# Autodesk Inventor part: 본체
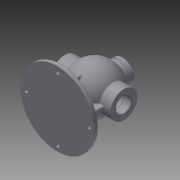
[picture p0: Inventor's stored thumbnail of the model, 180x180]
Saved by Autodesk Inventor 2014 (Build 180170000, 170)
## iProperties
Created: 2020-08
Part Number: 본체
Material: Generic
Document SubType Name: Modeling
Designer: kh
Density: 1 g/cm^3
Appearance: Default
Author: kh
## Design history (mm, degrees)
sketch "Sketch1"
  geometry: L1 (-53, 85)-(53, 85); A1 r 53 centre (0, 85) between (53, 85) and (-53, 85); 2 further points
  constraints: 2 end point, 2 horizontal alignment, 2 point on circle, 1 centre point, 1 midpoint, 1 vertical alignment
  dimensions: "d0" = 106 diameter of A1; "d1" = 85 distance of point (0, 0) A1.centre
revolve "Revolution1" sketch "Sketch1" stored, may be unused: angle "d2" = 90 deg
shell "Shell1" dims "d3" = 10
sketch "Sketch2"
  geometry: C1 r 85 at (0, 0); 1 further point
  constraints: 1 centre point, 1 coincident
  dimensions: "d4" = 170 diameter of C1
extrude "Extrusion1" join sketch "Sketch2" distance "d5" = 10; taper "d6" = 0 deg
workplane "Work Plane1"
sketch "Sketch3"
  geometry: C1 r 31 at (85, 0); 1 further point
  constraints: 1 centre point, 1 horizontal alignment
  dimensions: "d8" = 62 diameter of C1; "d9" = 85 distance of C1.centre point (0, 0)
extrude "Extrusion2" join sketch "Sketch3" stored distance "d10" = 10; taper "d11" = 0 deg
sketch "Sketch4"
  geometry: C1 r 31 at (0, 0) reference; C2 r 17.5 at (0, 0); 1 further point
  constraints: 1 centre point, 1 coincident
  dimensions: "d12" = 35 diameter of C2
extrude "Extrusion3" cut sketch "Sketch4" stored distance "d13" = 10; taper "d14" = 0 deg
sketch "Sketch5" dims "d15" = 48
  geometry: L1 (0, 0)-(0, 24); C1 r 31 at (0, 0) reference; 2 further points
  constraints: 2 coincident, 2 end point, 1 vertical, 1 vertical alignment, 2 other
hole "Hole1" sketch "Sketch5" at (0, 24) diameter "d16" = 3.242; stored, may be unused: countersink angle "d20" = 90 deg, drill point angle "d22" = 118 deg; dims "d17" = 12, "d18" = 4, "d19" = 2, "d21" = 15
pattern_circular "Circular Pattern1" dims angle "d24" = 360 deg
mirror "Mirror1"
workplane "Work Plane2"
sketch "Sketch6"
  geometry: C1 r 27 at (0, 0); 1 further point
  constraints: 1 centre point, 1 coincident
  dimensions: "d27" = 54 diameter of C1
extrude "Extrusion4" join sketch "Sketch6" stored distance "d28" = 10; taper "d29" = 0 deg
sketch "Sketch7"
  geometry: C1 r 13 at (0, 0); 1 further point
  constraints: 1 centre point, 1 coincident
  dimensions: "d30" = 26 diameter of C1
extrude "Extrusion5" cut sketch "Sketch7" stored distance "d31" = 10; taper "d32" = 0 deg
sketch "Sketch8" dims "d33" = 40
  geometry: L1 (0, 0)-(0, 20); C1 r 27 at (0, 0) reference; 2 further points
  constraints: 2 coincident, 2 end point, 1 vertical, 1 vertical alignment, 2 other
hole "Hole2" sketch "Sketch8" at (0, 20) diameter "d34" = 3.242; stored, may be unused: countersink angle "d38" = 90 deg, drill point angle "d40" = 118 deg; dims "d35" = 12, "d36" = 4, "d37" = 2, "d39" = 15
pattern_circular "Circular Pattern2" dims angle "d42" = 360 deg
workplane "Work Plane3"
sketch "Sketch9"
  geometry: C1 r 17.5 at (0, 0) reference; C2 r 18.5 at (0, 0); 1 further point
  constraints: 1 centre point, 1 coincident
  dimensions: "d45" = 37 diameter of C2
extrude "Extrusion6" cut sketch "Sketch9" distance "d46" = 1.75; taper "d47" = 0 deg
sketch "Sketch10"
  geometry: L1 (-52, 4)-(52, 4); L2 (52, 4)-(52, -4); L3 (52, -4)-(-52, -4); L4 (-52, -4)-(-52, 4); L5 (-4, 43)-(4, 43); L6 (4, 43)-(4, -43); L7 (4, -43)-(-4, -43); L8 (-4, -43)-(-4, 43); L9 (-52, 0)-(52, 0); L10 (0, 43)-(0, -43); 2 further points
  constraints: 20 end point, 6 midpoint, 4 parallel, 2 horizontal, 2 perpendicular, 1 coincident
  dimensions: "d48" = 104 distance of L2.end L3.end; "d49" = 86 distance of L5.end L6.end; "d50" = 8 distance of L3.end L1.start; "d51" = 8 distance of L5.start L5.end
extrude "Extrusion7" join sketch "Sketch10" stored distance "d52" = 1.75; taper "d53" = 0 deg
workplane "Work Plane4"
sketch "Sketch11"
  geometry: L1 (-27, 150)-(27, 150) reference; 2 further points
  constraints: 1 vertical alignment, 1 other
  dimensions: "d55" = 9 distance from line of point (0, 141) L1
emboss "Emboss1" sketch "Sketch11" dims "d0" = 106, "d1" = 85, "d12" = 35, "d56" = 0.5, "d57" = 0
sketch "Sketch12"
  geometry: L1 (-72.5, 0)-(72.5, 0); L2 (0, 72.5)-(0, -72.5); C1 r 4.5 at (-72.5, 0); C2 r 4.5 at (0, 72.5); C3 r 4.5 at (72.5, 0); C4 r 4.5 at (0, -72.5); A1 r 72.5 centre (0, 0) between (-72.5, 0) and (72.5, 0); 2 further points
  constraints: 6 coincident, 5 centre point, 4 end point, 4 point on circle, 3 equal radius, 2 midpoint, 1 horizontal, 1 perpendicular
  dimensions: "d58" = 145 diameter of A1; "d59" = 9 diameter of C1
extrude "Extrusion8" cut sketch "Sketch12" stored distance "d60" = 0; taper "d61" = 0 deg
chamfer "Chamfer1" distance "d62" = 1; stored, may be unused: second distance "d63" = 2, angle "d64" = 45 deg
fillet "Fillet1" dims "d65" = 3, "d66" = 3
fillet "Fillet2" dims "d67" = 3
body "Solid1"
other parameters: "d7" = 68, "d44" = -118.25, "d54" = 261.25
